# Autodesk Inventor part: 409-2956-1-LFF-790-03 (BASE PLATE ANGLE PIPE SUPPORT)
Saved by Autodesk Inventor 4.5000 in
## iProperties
Created: 2010-09
Part Number: 409-2956-1-LFF-790-03 (BASE PLATE ANGLE PIPE SUPPORT)
Cost Center: 0 lbmass
Material: A36 STEEL PLATE
Document SubType Name: Sheet Metal
Designer: S. Boerckel
Authority: 0 in^3
Mass: 2019.1 g
Surface Area: 484.956 cm^2
Volume: 256.883 cm^3
Density: 7.86 g/cm^3
Flat Pattern Width: 11.43 cm
Flat Pattern Length: 17.78 cm
Flat Pattern Area: 203.225 cm^2
Sheet Metal Rule: 1/2"Thk
Sheet Metal Width: 7.0000 in
Sheet Metal Length: 31.5000 in^2
Description: WELD PLATE
User Status: MACHINE
SaveDate: 2008-01-15
SaveTime: 10:24
FileName: Sheet Metal
Wide: =<Flat Pattern Width>cm
Length: =<Flat Pattern Length>cm
Thickness: 0.5000 in
SMR: =<Sheet Metal Rule> - <Material>
Author: S. Boerckel
Revision Number: 0
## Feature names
1. Hole1
2. Plate1
